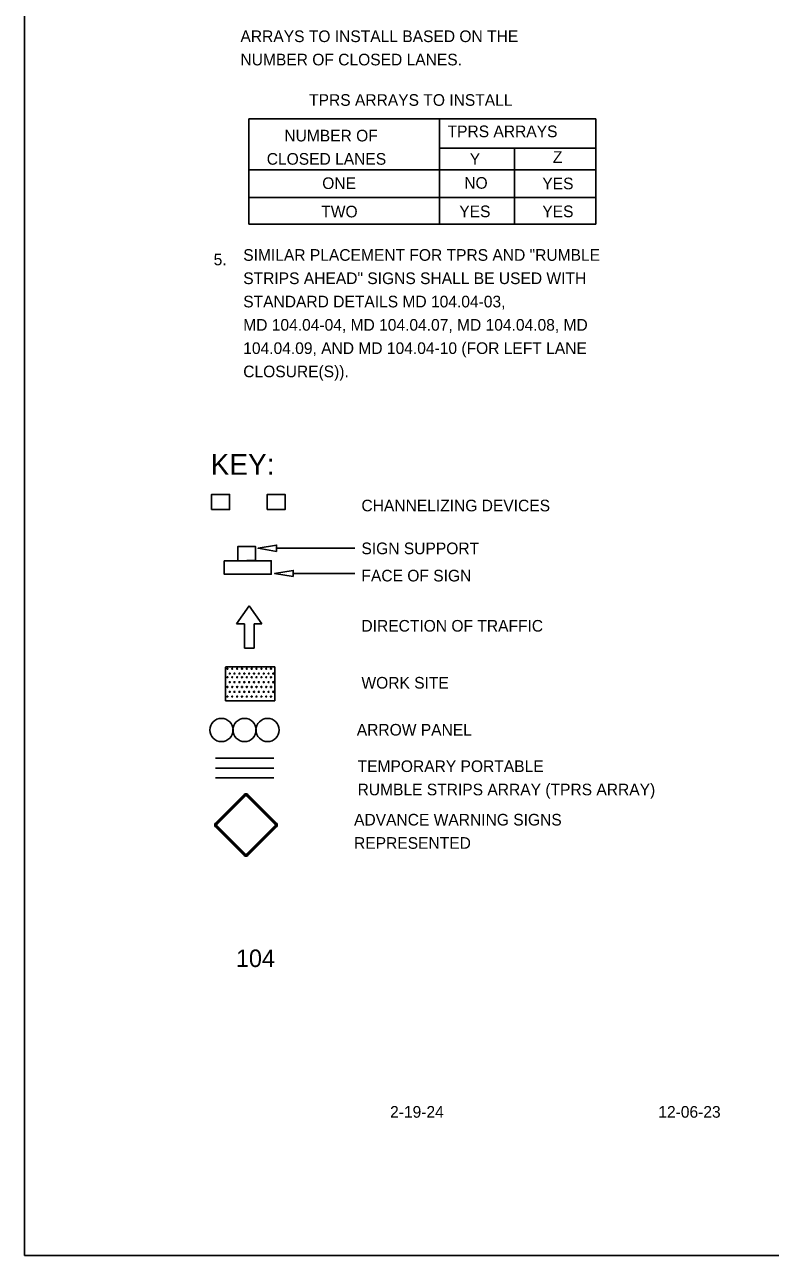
# Model space of a CAD drawing. Extents: x 0 to 1549163, y -476626 to 622136.
# Drawn here: x 11.44 to 15.28, y 5.67 to 12.01 of the extents above; entities that cross this region are included whole.
import ezdxf

# ---------------------------------------------------------------- set-up
doc = ezdxf.new("R2010")
doc.units = 0
for name, color, linetype in [('DETL-DIMS', 7, 'Continuous'), ('DETL-LINE', 7, 'Continuous'), ('DETL-NOTE', 7, 'Continuous'), ('DETL-TITL', 7, 'Continuous'), ('G-ANNO-LABL', 7, 'Continuous'), ('TTLB-TEXT', 7, 'Continuous'), ('USER-BORD', 7, 'Continuous'), ('USER-CLIP', 7, 'Continuous')]:
    doc.layers.add(name, color=color, linetype=linetype)

# ---------------------------------------------------------------- blocks, each defined once
blk = doc.blocks.new('PANEL0')
at = {"layer": 'USER-BORD'}
for centre in [(0.00309, -0.00012), (0.00928, -0.00012), (0.01546, -0.00012)]:
    blk.add_circle(centre, 0.00312, dxfattribs=at)
blk = doc.blocks.new('DIR4')
at = {"layer": 'USER-BORD'}
for p, q in [((0, 0.0001), (-0.0034, -0.0048)), ((0, 0.0001), (0.0034, -0.0048)), ((-0.0034, -0.0048), (-0.0013, -0.0048)), ((-0.0013, -0.0113), (-0.0013, -0.0048)), ((0.0034, -0.0048), (0.0013, -0.0048)), ((0.0013, -0.0113), (0.0013, -0.0048)), ((-0.0001, -0.0113), (-0.0013, -0.0113)), ((-0.0001, -0.0113), (0.0001, -0.0113)), ((0.0001, -0.0113), (0.0013, -0.0113))]:
    blk.add_line(p, q, dxfattribs=at)
blk = doc.blocks.new('SIGN15')
at = {"layer": 'USER-BORD'}
for points in [[(-0.0013, 0.0018), (0.0011, 0.0019), (0.0011, 0.0037), (-0.0013, 0.0037)], [(-0.0031, 0.0018), (-0.0031, 0), (0.0032, 0), (0.0032, 0.0018)]]:
    blk.add_lwpolyline(points, close=True, dxfattribs=at)

msp = doc.modelspace()

# ---------------------------------------------------------------- linework, layer by layer
at = {"layer": 'DETL-DIMS'}
for p, q in [((12.7364, 9.3098), (13.1387, 9.3098)), ((12.8219, 9.1802), (13.1387, 9.1802))]:
    msp.add_line(p, q, dxfattribs=at)
for points in [[(12.7364, 9.2935), (12.7364, 9.3262), (12.6404, 9.3098)], [(12.8219, 9.1639), (12.8219, 9.1956), (12.7259, 9.1802)]]:
    msp.add_lwpolyline(points, close=True, dxfattribs=at)
at = {"layer": 'DETL-LINE'}
for p, q in [((12.7274, 8.6984), (12.4734, 8.6984)), ((12.7274, 8.6984), (12.4734, 8.6984)), ((12.7274, 8.6984), (12.4734, 8.6984)), ((12.7274, 8.6984), (12.4734, 8.6984)), ((12.4734, 8.5243), (12.4734, 8.6983)), ((12.4734, 8.5243), (12.4734, 8.6983)), ((12.482, 8.6895), (12.482, 8.6895)), ((12.4828, 8.6895), (12.4828, 8.6895)), ((12.5076, 8.6895), (12.5076, 8.6895)), ((12.5076, 8.6895), (12.5076, 8.6895)), ((12.5324, 8.6895), (12.5324, 8.6895)), ((12.5332, 8.6895), (12.5332, 8.6895)), ((12.5572, 8.6895), (12.5572, 8.6895)), ((12.558, 8.6895), (12.558, 8.6895)), ((12.582, 8.6895), (12.582, 8.6895)), ((12.5828, 8.6895), (12.5828, 8.6895)), ((12.6076, 8.6895), (12.6076, 8.6895)), ((12.6076, 8.6895), (12.6076, 8.6895)), ((12.6324, 8.6895), (12.6324, 8.6895)), ((12.6324, 8.6895), (12.6324, 8.6895)), ((12.6572, 8.6895), (12.6572, 8.6895)), ((12.658, 8.6895), (12.658, 8.6895)), ((12.682, 8.6895), (12.682, 8.6895)), ((12.6828, 8.6895), (12.6828, 8.6895)), ((12.7076, 8.6895), (12.7076, 8.6895)), ((12.7076, 8.6895), (12.7076, 8.6895)), ((12.7274, 8.5244), (12.7274, 8.6984)), ((12.7274, 8.5244), (12.7274, 8.6984)), ((12.7274, 8.5244), (12.7274, 8.6984)), ((12.7274, 8.5244), (12.7274, 8.6984)), ((12.482, 8.6457), (12.482, 8.6457)), ((12.4828, 8.6457), (12.4828, 8.6457)), ((12.4948, 8.6647), (12.4948, 8.6647)), ((12.4948, 8.6647), (12.4948, 8.6647)), ((12.5076, 8.6457), (12.5076, 8.6457)), ((12.5076, 8.6457), (12.5076, 8.6457)), ((12.5196, 8.6647), (12.5196, 8.6647)), ((12.5196, 8.6647), (12.5196, 8.6647)), ((12.5324, 8.6457), (12.5324, 8.6457)), ((12.5332, 8.6457), (12.5332, 8.6457)), ((12.5452, 8.6647), (12.5452, 8.6647)), ((12.5452, 8.6647), (12.5452, 8.6647)), ((12.5572, 8.6457), (12.5572, 8.6457)), ((12.558, 8.6457), (12.558, 8.6457)), ((12.57, 8.6647), (12.57, 8.6647)), ((12.57, 8.6647), (12.57, 8.6647)), ((12.582, 8.6457), (12.582, 8.6457)), ((12.5828, 8.6457), (12.5828, 8.6457)), ((12.5948, 8.6647), (12.5948, 8.6647)), ((12.5948, 8.6647), (12.5948, 8.6647)), ((12.6076, 8.6457), (12.6076, 8.6457)), ((12.6076, 8.6457), (12.6076, 8.6457)), ((12.6196, 8.6647), (12.6196, 8.6647)), ((12.6196, 8.6647), (12.6196, 8.6647)), ((12.6324, 8.6457), (12.6324, 8.6457)), ((12.6324, 8.6457), (12.6324, 8.6457)), ((12.6444, 8.6647), (12.6444, 8.6647)), ((12.6444, 8.6647), (12.6444, 8.6647)), ((12.6572, 8.6457), (12.6572, 8.6457)), ((12.658, 8.6457), (12.658, 8.6457)), ((12.67, 8.6647), (12.67, 8.6647)), ((12.67, 8.6647), (12.67, 8.6647)), ((12.682, 8.6457), (12.682, 8.6457)), ((12.6828, 8.6457), (12.6828, 8.6457)), ((12.6948, 8.6647), (12.6948, 8.6647)), ((12.6948, 8.6647), (12.6948, 8.6647)), ((12.7076, 8.6457), (12.7076, 8.6457)), ((12.7076, 8.6457), (12.7076, 8.6457)), ((12.7196, 8.6647), (12.7196, 8.6647)), ((12.7196, 8.6647), (12.7196, 8.6647)), ((12.482, 8.5953), (12.482, 8.5953)), ((12.4828, 8.5953), (12.4828, 8.5953)), ((12.4948, 8.6201), (12.4948, 8.6201)), ((12.4948, 8.5705), (12.4948, 8.5705)), ((12.4948, 8.5705), (12.4948, 8.5705)), ((12.5076, 8.5953), (12.5076, 8.5953)), ((12.5076, 8.5953), (12.5076, 8.5953)), ((12.5196, 8.6201), (12.5196, 8.6201)), ((12.5196, 8.5705), (12.5196, 8.5705)), ((12.5196, 8.5705), (12.5196, 8.5705)), ((12.5324, 8.5953), (12.5324, 8.5953)), ((12.5332, 8.5953), (12.5332, 8.5953)), ((12.5452, 8.6201), (12.5452, 8.6201)), ((12.5452, 8.5705), (12.5452, 8.5705)), ((12.5452, 8.5705), (12.5452, 8.5705)), ((12.5572, 8.5953), (12.5572, 8.5953)), ((12.558, 8.5953), (12.558, 8.5953)), ((12.57, 8.6201), (12.57, 8.6201)), ((12.57, 8.5705), (12.57, 8.5705)), ((12.57, 8.5705), (12.57, 8.5705)), ((12.582, 8.5953), (12.582, 8.5953)), ((12.5828, 8.5953), (12.5828, 8.5953)), ((12.5948, 8.6201), (12.5948, 8.6201)), ((12.5948, 8.5705), (12.5948, 8.5705)), ((12.5948, 8.5705), (12.5948, 8.5705)), ((12.6076, 8.5953), (12.6076, 8.5953)), ((12.6076, 8.5953), (12.6076, 8.5953)), ((12.6196, 8.6201), (12.6196, 8.6201)), ((12.6196, 8.5705), (12.6196, 8.5705)), ((12.6196, 8.5705), (12.6196, 8.5705)), ((12.6324, 8.5953), (12.6324, 8.5953)), ((12.6324, 8.5953), (12.6324, 8.5953)), ((12.6444, 8.6201), (12.6444, 8.6201)), ((12.6444, 8.5705), (12.6444, 8.5705)), ((12.6444, 8.5705), (12.6444, 8.5705)), ((12.6572, 8.5953), (12.6572, 8.5953)), ((12.658, 8.5953), (12.658, 8.5953)), ((12.67, 8.6201), (12.67, 8.6201)), ((12.67, 8.5705), (12.67, 8.5705)), ((12.67, 8.5705), (12.67, 8.5705)), ((12.682, 8.5953), (12.682, 8.5953)), ((12.6828, 8.5953), (12.6828, 8.5953)), ((12.6948, 8.6201), (12.6948, 8.6201)), ((12.6948, 8.5705), (12.6948, 8.5705)), ((12.6948, 8.5705), (12.6948, 8.5705)), ((12.7076, 8.5953), (12.7076, 8.5953)), ((12.7076, 8.5953), (12.7076, 8.5953)), ((12.7196, 8.6201), (12.7196, 8.6201)), ((12.7196, 8.5705), (12.7196, 8.5705)), ((12.7196, 8.5705), (12.7196, 8.5705)), ((12.4734, 8.5243), (12.7274, 8.5243)), ((12.482, 8.5461), (12.482, 8.5461)), ((12.4828, 8.5461), (12.4828, 8.5461)), ((12.5076, 8.5461), (12.5076, 8.5461)), ((12.5076, 8.5461), (12.5076, 8.5461)), ((12.5324, 8.5461), (12.5324, 8.5461)), ((12.5332, 8.5461), (12.5332, 8.5461)), ((12.5572, 8.5461), (12.5572, 8.5461)), ((12.558, 8.5461), (12.558, 8.5461)), ((12.582, 8.5461), (12.582, 8.5461)), ((12.5828, 8.5461), (12.5828, 8.5461)), ((12.6076, 8.5461), (12.6076, 8.5461)), ((12.6076, 8.5461), (12.6076, 8.5461)), ((12.6324, 8.5461), (12.6324, 8.5461)), ((12.6324, 8.5461), (12.6324, 8.5461)), ((12.6572, 8.5461), (12.6572, 8.5461)), ((12.658, 8.5461), (12.658, 8.5461)), ((12.682, 8.5461), (12.682, 8.5461)), ((12.6828, 8.5461), (12.6828, 8.5461)), ((12.7076, 8.5461), (12.7076, 8.5461)), ((12.7076, 8.5461), (12.7076, 8.5461)), ((12.4217, 8.2279), (12.7217, 8.2279)), ((12.4217, 8.1779), (12.7217, 8.1779)), ((12.4217, 8.1279), (12.7217, 8.1279))]:
    msp.add_line(p, q, dxfattribs=at)
for points in [[(12.4014, 9.5095), (12.4014, 9.5873), (12.4935, 9.5873), (12.4935, 9.5095)], [(12.6875, 9.5095), (12.6875, 9.5873), (12.7796, 9.5873), (12.7796, 9.5095)]]:
    msp.add_lwpolyline(points, close=True, dxfattribs=at)
for centre in [(12.4827, 8.6893), (12.5075, 8.6893), (12.5331, 8.6893), (12.5579, 8.6893), (12.5827, 8.6893), (12.6075, 8.6893), (12.6323, 8.6893), (12.6579, 8.6893), (12.6827, 8.6893), (12.7075, 8.6893), (12.4827, 8.6456), (12.4947, 8.6645), (12.4947, 8.62), (12.5075, 8.6456), (12.5195, 8.6645), (12.5195, 8.62), (12.5331, 8.6456), (12.5451, 8.6645), (12.5451, 8.62), (12.5579, 8.6456), (12.5699, 8.6645), (12.5699, 8.62), (12.5827, 8.6456), (12.5947, 8.6645), (12.5947, 8.62), (12.6075, 8.6456), (12.6195, 8.6645), (12.6195, 8.62), (12.6323, 8.6456), (12.6443, 8.6645), (12.6443, 8.62), (12.6579, 8.6456), (12.6699, 8.6645), (12.6699, 8.62), (12.6827, 8.6456), (12.6947, 8.6645), (12.6947, 8.62), (12.7075, 8.6456), (12.7195, 8.6645), (12.7195, 8.62), (12.4827, 8.5952), (12.4947, 8.5704), (12.5075, 8.5952), (12.5195, 8.5704), (12.5331, 8.5952), (12.5451, 8.5704), (12.5579, 8.5952), (12.5699, 8.5704), (12.5827, 8.5952), (12.5947, 8.5704), (12.6075, 8.5952), (12.6195, 8.5704), (12.6323, 8.5952), (12.6443, 8.5704), (12.6579, 8.5952), (12.6699, 8.5704), (12.6827, 8.5952), (12.6947, 8.5704), (12.7075, 8.5952), (12.7195, 8.5704), (12.4827, 8.546), (12.5075, 8.546), (12.5331, 8.546), (12.5579, 8.546), (12.5827, 8.546), (12.6075, 8.546), (12.6323, 8.546), (12.6579, 8.546), (12.6827, 8.546), (12.7075, 8.546)]:
    msp.add_circle(centre, 0.00291, dxfattribs=at)
at = {"layer": 'DETL-NOTE'}
for p, q in [((12.5931, 11.5222), (12.5931, 10.9798)), ((12.5931, 11.5222), (14.3808, 11.5222)), ((13.5762, 11.5222), (13.5762, 10.9798)), ((14.3808, 11.5222), (14.3808, 10.9798)), ((13.5762, 11.371), (14.3808, 11.371)), ((13.9626, 11.371), (13.9626, 10.9798)), ((12.5931, 11.2599), (14.3808, 11.2599)), ((12.5931, 11.1175), (14.3808, 11.1175)), ((12.5931, 10.9798), (14.3808, 10.9798))]:
    msp.add_line(p, q, dxfattribs=at)
at = {"layer": 'DETL-TITL'}
for p, q in [((12.5691, 8.0415), (12.4213, 7.8936)), ((12.5718, 8.0388), (12.4239, 7.8909)), ((12.428, 7.8868), (12.5759, 8.0347)), ((12.5809, 8.0347), (12.7287, 7.8868)), ((12.7329, 7.8909), (12.585, 8.0388)), ((12.7355, 7.8936), (12.5877, 8.0415)), ((12.4213, 7.875), (12.5691, 7.7273)), ((12.4239, 7.8777), (12.5718, 7.7298)), ((12.5759, 7.7339), (12.428, 7.8818)), ((12.7287, 7.8818), (12.5809, 7.7339)), ((12.585, 7.7298), (12.7329, 7.8777)), ((12.5877, 7.7273), (12.7355, 7.875))]:
    msp.add_line(p, q, dxfattribs=at)
for centre, radius, start, end in [((12.5784, 8.0321), 0.0131, 45, 135), ((12.5784, 8.0321), 0.00939, 45, 135), ((12.5784, 8.0321), 0.00357, 45, 135), ((12.4306, 7.8843), 0.0131, 135, 225), ((12.4306, 7.8843), 0.00939, 135, 225), ((12.4306, 7.8843), 0.00357, 135, 225), ((12.7262, 7.8843), 0.00357, 315, 45), ((12.7262, 7.8843), 0.00939, 315, 45), ((12.7262, 7.8843), 0.0131, 315, 45), ((12.5784, 7.7365), 0.0131, 225, 315), ((12.5784, 7.7365), 0.00939, 225, 315), ((12.5784, 7.7365), 0.00357, 225, 315)]:
    msp.add_arc(centre, radius, start, end, dxfattribs=at)
at = {"layer": 'USER-CLIP'}
msp.add_lwpolyline([(19.9377, 16.6675), (11.4377, 16.6675), (11.4377, 5.6675), (19.9377, 5.6675)], close=True, dxfattribs=at)

# ---------------------------------------------------------------- block references
at = {"layer": 'DETL-LINE'}
for name, p, xscale, yscale in [('SIGN15', (12.5857, 9.1764), 38.4, 38.4), ('DIR4', (12.5953, 9.0122), 19.2, 19.2), ('PANEL0', (12.3927, 8.3761), 19.2, 19.2)]:
    msp.add_blockref(name, p, dxfattribs=dict(at, xscale=xscale, yscale=yscale))

# ---------------------------------------------------------------- texts
at = {"layer": 'DETL-NOTE'}
for s, p in [('ARRAYS TO INSTALL BASED ON THE ', (12.5499, 11.9173)), ('NUMBER OF CLOSED LANES.', (12.5499, 11.7973)), ('TPRS ARRAYS TO INSTALL', (12.9036, 11.589)), ('TPRS ARRAYS', (13.6171, 11.4275)), ('NUMBER OF', (12.7759, 11.4056)), ('Z', (14.1594, 11.2953)), ('CLOSED LANES', (12.6853, 11.2856)), ('Y', (13.7313, 11.2851)), ('NO', (13.7031, 11.1619)), ('ONE', (12.9712, 11.1605)), ('YES', (14.1052, 11.159)), ('TWO', (12.9663, 11.0143)), ('YES', (13.6774, 11.0154)), ('YES', (14.1052, 11.0154)), ('SIMILAR PLACEMENT FOR TPRS AND "RUMBLE ', (12.5642, 10.7907)), ('5.', (12.4118, 10.7676)), ('STRIPS AHEAD" SIGNS SHALL BE USED WITH ', (12.5642, 10.6707)), ('STANDARD DETAILS MD 104.04-03,', (12.5642, 10.5507)), ('MD 104.04-04, MD 104.04.07, MD 104.04.08, MD ', (12.5642, 10.4307)), ('104.04.09, AND MD 104.04-10 (FOR LEFT LANE ', (12.5642, 10.3107)), ('CLOSURE(S)).', (12.5642, 10.1907)), ('CHANNELIZING DEVICES', (13.1732, 9.5001)), ('SIGN SUPPORT', (13.1732, 9.2794)), ('FACE OF SIGN', (13.1732, 9.139)), ('DIRECTION OF TRAFFIC', (13.1732, 8.8805)), ('WORK SITE', (13.1732, 8.5871)), ('ARROW PANEL', (13.1492, 8.345)), ('TEMPORARY PORTABLE', (13.1534, 8.1573)), ('RUMBLE STRIPS ARRAY (TPRS ARRAY)', (13.1534, 8.0373)), ('ADVANCE WARNING SIGNS ', (13.1352, 7.8818)), ('REPRESENTED', (13.1352, 7.7618))]:
    msp.add_text(s, height=0.06, dxfattribs=at).set_placement(p)
at = {"layer": 'DETL-TITL'}
msp.add_text('KEY:', height=0.108, dxfattribs=at).set_placement((12.3961, 9.6882))
at = {"layer": 'G-ANNO-LABL'}
msp.add_text('2-19-24', height=0.06, dxfattribs=at).set_placement((13.3209, 6.3767))
at = {"layer": 'TTLB-TEXT'}
for s, height, p in [('104', 0.09, (12.5267, 7.1528)), ('12-06-23', 0.06, (14.7028, 6.3767))]:
    msp.add_text(s, height=height, dxfattribs=at).set_placement(p)

doc.saveas('drawing.dxf')
